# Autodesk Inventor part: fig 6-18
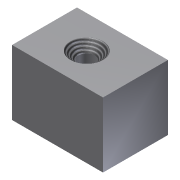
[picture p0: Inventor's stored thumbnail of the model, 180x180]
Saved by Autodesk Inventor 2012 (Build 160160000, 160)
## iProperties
Created: 2009-09
Part Number: fig 6-18
Document SubType Name: Modeling
Designer: Sham
Density: 1 g/cm^3
Material: Default
Author: Sham
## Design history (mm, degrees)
sketch "Sketch1"
  geometry: L1 (-28, 20)-(0, 20); L2 (0, 20)-(0, 0); L3 (0, 0)-(-28, 0); L4 (-28, 0)-(-28, 20)
  constraints: 8 end point, 2 parallel, 1 horizontal, 1 perpendicular
extrude "Extrusion1" new body sketch "Sketch1" distance "d0" = 20; taper "d1" = 0 deg
hole "Hole1" diameter "d4" = 5; stored, may be unused: countersink angle "d8" = 90 deg, drill point angle "d10" = 118 deg; dims "d2" = 10, "d3" = 15, "d5" = 5.946, "d6" = 10, "d7" = 3, "d9" = 15, "d11" = 0.62479, "d12" = 5.994
thread "Thread1" dims "d13" = 10, "d14" = 0
body "Solid1"
